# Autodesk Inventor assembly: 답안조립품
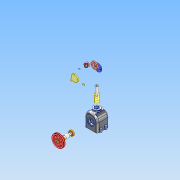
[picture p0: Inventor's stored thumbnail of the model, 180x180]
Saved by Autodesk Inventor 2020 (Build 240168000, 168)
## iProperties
Created: 2023-03
Part Number: 답안조립품
Document SubType Name: Assembly
Designer: user
Author: user
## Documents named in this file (22)
- C:\Users\user\Desktop\730306V1016\답안조립품.iam
- C:\Users\user\Desktop\730306V1016\본체.ipt
- C:\Users\user\Desktop\730306V1016\E형 멈춤링 13 x 12.ipt
- C:\Users\user\Desktop\730306V1016\V-벨트풀리.ipt
- C:\Users\user\Desktop\730306V1016\고정핀.ipt
- C:\Users\user\Desktop\730306V1016\뒷커버.ipt
- C:\Users\user\Desktop\730306V1016\링크.ipt
- C:\Users\user\Desktop\730306V1016\멈춤링 25 x 1.2.ipt
- 멈춤링 25 x 1.2.ipt
- C:\Users\user\Desktop\730306V1016\베어링 6205.ipt
- 베어링 6205.ipt
- C:\Users\user\Desktop\730306V1016\볼트 M4 x 12.ipt
- C:\Users\user\Desktop\730306V1016\볼트 M8 x 16.ipt
- C:\Users\user\Desktop\730306V1016\부시.ipt
- C:\Users\user\Desktop\730306V1016\슬라이더.ipt
- C:\Users\user\Desktop\730306V1016\앞커버.ipt
- C:\Users\user\Desktop\730306V1016\엔드캡.ipt
- C:\Users\user\Desktop\730306V1016\오일실 25 40 8.ipt
- 오일실 25 40 8.ipt
- C:\Users\user\Desktop\730306V1016\윗커버.ipt
- C:\Users\user\Desktop\730306V1016\키 6x6x14.ipt
- C:\Users\user\Desktop\730306V1016\편심축.ipt
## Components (3 placed, 3 different names)
1. E형 멈춤링 13 x 12:1
2. V-벨트풀리:1
3. 고정핀:1
